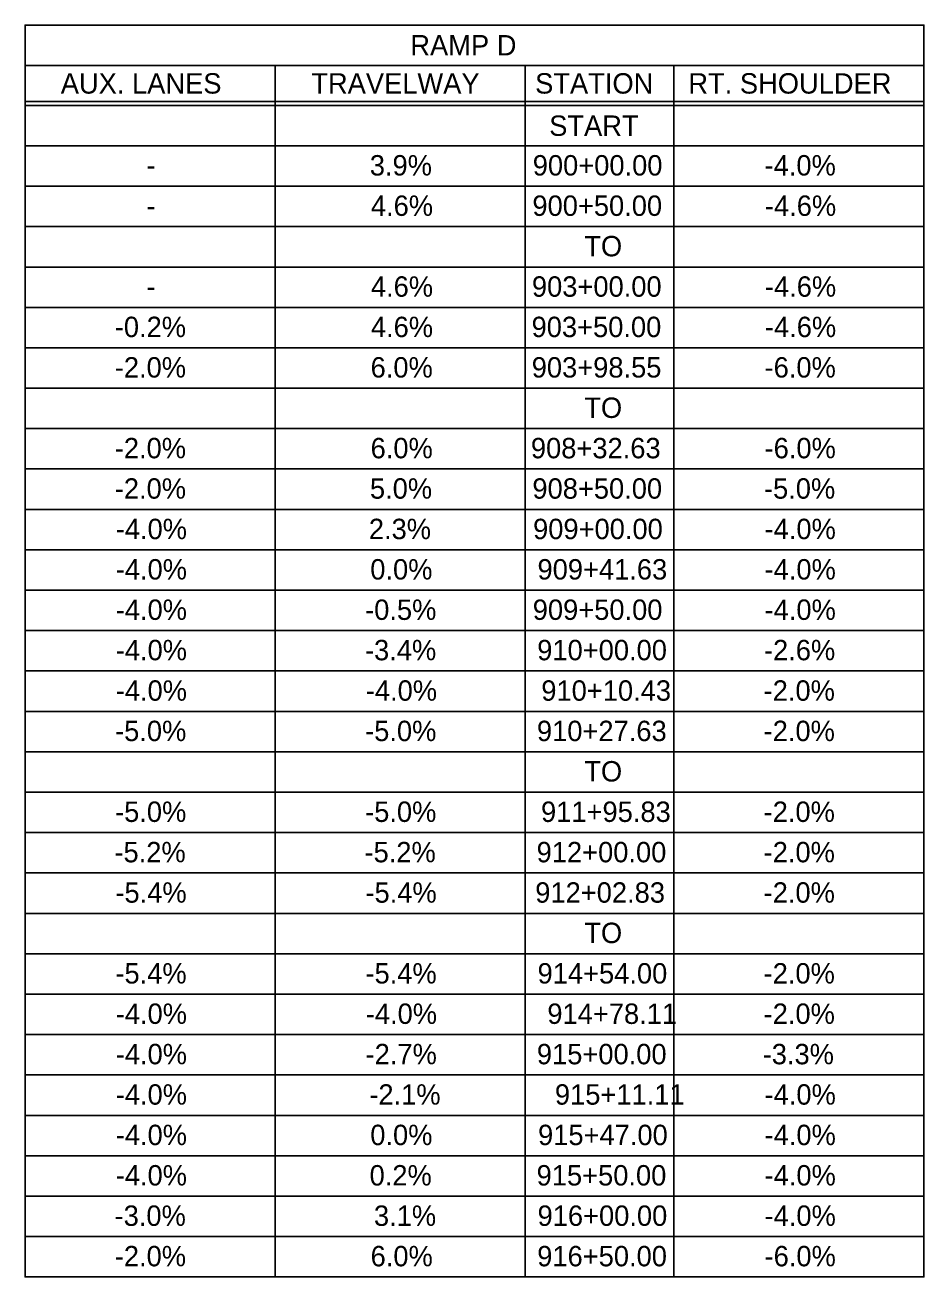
# Model space of a CAD drawing. Extents: x -15319374 to 1762012, y 465773 to 3693661.
# Drawn here: x -15319212.4 to -15319080.2, y 3691807.8 to 3691992 of the extents above; entities that cross this region are included whole.
import ezdxf

# ---------------------------------------------------------------- set-up
doc = ezdxf.new("R2010")
doc.units = 0
doc.layers.add('BORDER', color=7, linetype='Continuous')
doc.layers.add('DIMENSIONS', color=7, linetype='Continuous')

msp = doc.modelspace()

# ---------------------------------------------------------------- linework, layer by layer
at = {"layer": 'BORDER'}
for p, q in [((-15319212.39, 3691986.01), (-15319212.39, 3691867.81)), ((-15319175.62, 3691986.01), (-15319175.62, 3691807.8)), ((-15319138.86, 3691986.01), (-15319138.86, 3691807.8)), ((-15319116.98, 3691986.01), (-15319116.98, 3691807.8)), ((-15319212.39, 3691980.73), (-15319080.21, 3691980.73)), ((-15319212.39, 3691980.13), (-15319080.21, 3691980.13)), ((-15319212.39, 3691974.19), (-15319080.21, 3691974.19)), ((-15319212.39, 3691974.19), (-15319080.21, 3691974.19)), ((-15319212.39, 3691974.19), (-15319080.21, 3691974.19)), ((-15319212.39, 3691968.25), (-15319080.21, 3691968.25)), ((-15319212.39, 3691962.31), (-15319080.21, 3691962.31)), ((-15319212.39, 3691956.36), (-15319080.21, 3691956.36)), ((-15319212.39, 3691950.42), (-15319080.21, 3691950.42)), ((-15319212.39, 3691944.48), (-15319080.21, 3691944.48)), ((-15319212.39, 3691938.53), (-15319080.21, 3691938.53)), ((-15319212.39, 3691932.59), (-15319080.21, 3691932.59)), ((-15319212.39, 3691926.65), (-15319080.21, 3691926.65)), ((-15319212.39, 3691920.71), (-15319080.21, 3691920.71)), ((-15319212.39, 3691914.76), (-15319080.21, 3691914.76)), ((-15319212.39, 3691908.82), (-15319080.21, 3691908.82)), ((-15319212.39, 3691902.88), (-15319080.21, 3691902.88)), ((-15319212.39, 3691896.94), (-15319080.21, 3691896.94)), ((-15319212.39, 3691890.99), (-15319080.21, 3691890.99)), ((-15319212.39, 3691885.05), (-15319080.21, 3691885.05)), ((-15319212.39, 3691879.11), (-15319080.21, 3691879.11)), ((-15319212.39, 3691873.17), (-15319080.21, 3691873.17)), ((-15319212.39, 3691867.22), (-15319080.21, 3691867.22)), ((-15319212.39, 3691861.28), (-15319080.21, 3691861.28)), ((-15319212.39, 3691855.34), (-15319080.21, 3691855.34)), ((-15319212.39, 3691849.39), (-15319080.21, 3691849.39)), ((-15319212.39, 3691843.45), (-15319080.21, 3691843.45)), ((-15319212.39, 3691837.51), (-15319080.21, 3691837.51)), ((-15319212.39, 3691831.57), (-15319080.21, 3691831.57)), ((-15319212.39, 3691825.62), (-15319080.21, 3691825.62)), ((-15319212.39, 3691819.68), (-15319080.21, 3691819.68)), ((-15319212.39, 3691813.74), (-15319080.21, 3691813.74))]:
    msp.add_line(p, q, dxfattribs=at)
msp.add_lwpolyline([(-15319212.39, 3691986.01), (-15319212.39, 3691991.95), (-15319080.21, 3691991.95), (-15319080.21, 3691986.01)], dxfattribs=at)
msp.add_lwpolyline([(-15319212.39, 3691986.01), (-15319080.21, 3691986.01), (-15319080.21, 3691807.8), (-15319212.39, 3691807.8)], close=True, dxfattribs=at)

# ---------------------------------------------------------------- texts
at = {"layer": 'DIMENSIONS'}
for s, p in [('RAMP D', (-15319155.74, 3691987.48)), ('AUX. LANES', (-15319207.14, 3691981.87)), ('TRAVELWAY', (-15319170.3, 3691981.87)), ('STATION', (-15319137.39, 3691981.87)), ('RT. SHOULDER', (-15319114.86, 3691981.87)), ('START', (-15319135.32, 3691975.65)), ('3.9%', (-15319161.7, 3691969.82)), ('900+00.00', (-15319137.74, 3691969.82)), ('-4.0%', (-15319103.65, 3691969.82)), ('-', (-15319194.52, 3691969.82)), ('-', (-15319194.52, 3691963.88)), ('4.6%', (-15319161.54, 3691963.88)), ('900+50.00', (-15319137.79, 3691963.88)), ('-4.6%', (-15319103.6, 3691963.88)), ('TO', (-15319130.16, 3691957.93)), ('4.6%', (-15319161.54, 3691951.99)), ('903+00.00', (-15319137.86, 3691951.99)), ('-4.6%', (-15319103.6, 3691951.99)), ('-', (-15319194.52, 3691951.99)), ('-0.2%', (-15319199.2, 3691946.05)), ('4.6%', (-15319161.54, 3691946.05)), ('903+50.00', (-15319137.91, 3691946.05)), ('-4.6%', (-15319103.6, 3691946.05)), ('-2.0%', (-15319199.2, 3691940.1)), ('6.0%', (-15319161.58, 3691940.1)), ('903+98.55', (-15319137.89, 3691940.1)), ('-6.0%', (-15319103.65, 3691940.1)), ('TO', (-15319130.16, 3691934.16)), ('-2.0%', (-15319199.2, 3691928.22)), ('6.0%', (-15319161.58, 3691928.22)), ('908+32.63', (-15319138.01, 3691928.22)), ('-6.0%', (-15319103.65, 3691928.22)), ('-2.0%', (-15319199.2, 3691922.28)), ('5.0%', (-15319161.68, 3691922.28)), ('908+50.00', (-15319137.79, 3691922.28)), ('-5.0%', (-15319103.74, 3691922.28)), ('-4.0%', (-15319199.06, 3691916.33)), ('2.3%', (-15319161.84, 3691916.33)), ('909+00.00', (-15319137.69, 3691916.33)), ('-4.0%', (-15319103.65, 3691916.33)), ('-4.0%', (-15319199.06, 3691910.39)), ('0.0%', (-15319161.63, 3691910.39)), ('909+41.63', (-15319137.04, 3691910.39)), ('-4.0%', (-15319103.65, 3691910.39)), ('-4.0%', (-15319199.06, 3691904.45)), ('-0.5%', (-15319162.39, 3691904.45)), ('909+50.00', (-15319137.74, 3691904.45)), ('-4.0%', (-15319103.65, 3691904.45)), ('-4.0%', (-15319199.06, 3691898.51)), ('-3.4%', (-15319162.41, 3691898.51)), ('910+00.00', (-15319137.08, 3691898.51)), ('-2.6%', (-15319103.74, 3691898.51)), ('-4.0%', (-15319199.06, 3691892.56)), ('-4.0%', (-15319162.29, 3691892.56)), ('910+10.43', (-15319136.48, 3691892.56)), ('-2.0%', (-15319103.79, 3691892.56)), ('-5.0%', (-15319199.16, 3691886.62)), ('-5.0%', (-15319162.39, 3691886.62)), ('910+27.63', (-15319137.12, 3691886.62)), ('-2.0%', (-15319103.79, 3691886.62)), ('TO', (-15319130.16, 3691880.68)), ('-5.0%', (-15319199.16, 3691874.73)), ('-5.0%', (-15319162.39, 3691874.73)), ('911+95.83', (-15319136.52, 3691874.73)), ('-2.0%', (-15319103.79, 3691874.73)), ('-5.2%', (-15319199.25, 3691868.79)), ('-5.2%', (-15319162.48, 3691868.79)), ('912+00.00', (-15319137.17, 3691868.79)), ('-2.0%', (-15319103.79, 3691868.79)), ('-5.4%', (-15319199.11, 3691862.85)), ('-5.4%', (-15319162.34, 3691862.85)), ('912+02.83', (-15319137.37, 3691862.85)), ('-2.0%', (-15319103.79, 3691862.85)), ('TO', (-15319130.16, 3691856.91)), ('-5.4%', (-15319199.11, 3691850.96)), ('-5.4%', (-15319162.34, 3691850.96)), ('914+54.00', (-15319137.03, 3691850.96)), ('-2.0%', (-15319103.79, 3691850.96)), ('-4.0%', (-15319199.06, 3691845.02)), ('-4.0%', (-15319162.29, 3691845.02)), ('914+78.11', (-15319135.59, 3691845.02)), ('-2.0%', (-15319103.79, 3691845.02)), ('-4.0%', (-15319199.06, 3691839.08)), ('-2.7%', (-15319162.32, 3691839.08)), ('915+00.00', (-15319137.13, 3691839.08)), ('-3.3%', (-15319103.93, 3691839.08)), ('-4.0%', (-15319199.06, 3691833.14)), ('-2.1%', (-15319161.77, 3691833.14)), ('915+11.11', (-15319134.48, 3691833.14)), ('-4.0%', (-15319103.65, 3691833.14)), ('-4.0%', (-15319199.06, 3691827.19)), ('0.0%', (-15319161.63, 3691827.19)), ('915+47.00', (-15319136.96, 3691827.19)), ('-4.0%', (-15319103.65, 3691827.19)), ('-4.0%', (-15319199.06, 3691821.25)), ('0.2%', (-15319161.73, 3691821.25)), ('915+50.00', (-15319137.17, 3691821.25)), ('-4.0%', (-15319103.65, 3691821.25)), ('-3.0%', (-15319199.23, 3691815.31)), ('3.1%', (-15319161.09, 3691815.31)), ('916+00.00', (-15319137.03, 3691815.31)), ('-4.0%', (-15319103.65, 3691815.31)), ('-2.0%', (-15319199.2, 3691809.36)), ('6.0%', (-15319161.58, 3691809.36)), ('916+50.00', (-15319137.08, 3691809.36)), ('-6.0%', (-15319103.65, 3691809.36))]:
    msp.add_text(s, height=3, dxfattribs=at).set_placement(p)

doc.saveas('drawing.dxf')
